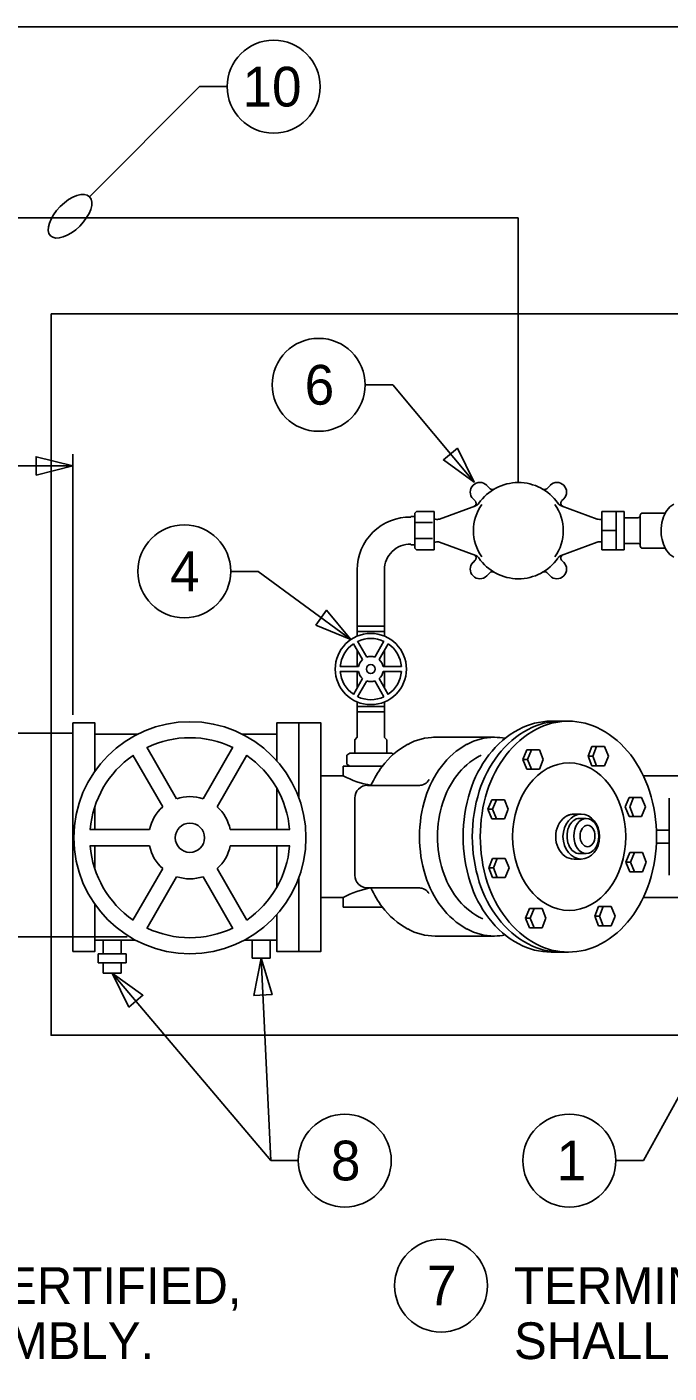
# Model space of a CAD drawing. Extents: x 10462 to 10511.2, y 10121.5 to 10170.9.
# Drawn here: x 10480.39 to 10492.04, y 10146.47 to 10170.89 of the extents above; entities that cross this region are included whole.
import ezdxf

# ---------------------------------------------------------------- set-up
doc = ezdxf.new("R2010")
doc.units = 0
for name, color, linetype in [('G-ANNO-NPLT', 7, 'Continuous'), ('G-ANNO-SYMB', 7, 'Continuous'), ('G-DETL-LINE', 7, 'Continuous'), ('G-DETL-TEXT', 7, 'Continuous')]:
    doc.layers.add(name, color=color, linetype=linetype)

msp = doc.modelspace()

# ---------------------------------------------------------------- linework, layer by layer
at = {"layer": 'G-ANNO-NPLT'}
msp.add_lwpolyline([(10462.021, 10170.89), (10511.163, 10170.89), (10511.163, 10125.39), (10462.021, 10125.39)], close=True, dxfattribs=at)
at = {"layer": 'G-ANNO-SYMB'}
for centre in [(10484.866, 10169.807), (10485.682, 10164.398), (10483.244, 10161.015), (10486.156, 10150.327), (10490.229, 10150.327), (10487.902, 10148.059)]:
    msp.add_circle(centre, 0.843, dxfattribs=at)
at = {"layer": 'G-DETL-LINE'}
for p, q in [((10469.431, 10167.426), (10489.303, 10167.426)), ((10489.303, 10162.626), (10489.303, 10167.426)), ((10486.525, 10164.398), (10487.025, 10164.398)), ((10488.501, 10162.632), (10487.025, 10164.398)), ((10488.73, 10162.575), (10488.791, 10162.514)), ((10489.88, 10162.575), (10489.819, 10162.514)), ((10487.875, 10161.964), (10488.531, 10162.206)), ((10488.483, 10162.328), (10488.521, 10162.291)), ((10490.735, 10161.964), (10490.079, 10162.206)), ((10490.127, 10162.328), (10490.089, 10162.291)), ((10487.355, 10162.011), (10487.428, 10162.011)), ((10487.428, 10162.073), (10487.457, 10162.103)), ((10487.428, 10162.073), (10487.428, 10161.433)), ((10487.744, 10161.899), (10487.428, 10161.899)), ((10487.777, 10162.103), (10487.457, 10162.103)), ((10487.777, 10162.103), (10487.777, 10161.899)), ((10487.777, 10161.899), (10487.777, 10161.753)), ((10487.835, 10161.957), (10487.817, 10161.957)), ((10490.775, 10161.957), (10490.793, 10161.957)), ((10490.817, 10161.404), (10490.817, 10162.103)), ((10490.817, 10162.103), (10491.224, 10162.103)), ((10491.079, 10161.404), (10491.079, 10162.103)), ((10491.224, 10161.404), (10491.224, 10162.103)), ((10491.474, 10161.986), (10491.224, 10161.986)), ((10491.515, 10161.479), (10491.515, 10162.031)), ((10491.515, 10162.028), (10491.515, 10162.031)), ((10491.557, 10162.073), (10491.971, 10162.073)), ((10487.777, 10161.753), (10487.777, 10161.404)), ((10490.817, 10161.753), (10491.079, 10161.753)), ((10487.355, 10161.495), (10487.428, 10161.495)), ((10487.744, 10161.608), (10487.428, 10161.608)), ((10487.428, 10161.433), (10487.457, 10161.404)), ((10487.835, 10161.55), (10487.817, 10161.55)), ((10487.875, 10161.542), (10488.531, 10161.301)), ((10490.735, 10161.542), (10490.079, 10161.301)), ((10490.775, 10161.55), (10490.793, 10161.55)), ((10491.474, 10161.521), (10491.224, 10161.521)), ((10491.515, 10161.475), (10491.515, 10161.479)), ((10491.557, 10161.433), (10491.971, 10161.433)), ((10487.777, 10161.404), (10487.457, 10161.404)), ((10488.483, 10161.178), (10488.521, 10161.216)), ((10490.127, 10161.178), (10490.089, 10161.216)), ((10490.817, 10161.404), (10491.224, 10161.404)), ((10484.087, 10161.015), (10484.587, 10161.015)), ((10486.263, 10159.779), (10484.587, 10161.015)), ((10486.381, 10161.041), (10486.381, 10159.84)), ((10486.875, 10161.041), (10486.875, 10159.84)), ((10488.73, 10160.931), (10488.791, 10160.992)), ((10489.88, 10160.931), (10489.819, 10160.992)), ((10486.381, 10160.022), (10486.875, 10160.022)), ((10486.477, 10159.415), (10486.311, 10159.703)), ((10486.381, 10159.925), (10486.875, 10159.925)), ((10486.554, 10159.46), (10486.388, 10159.748)), ((10486.867, 10159.748), (10486.701, 10159.46)), ((10486.945, 10159.703), (10486.779, 10159.415)), ((10486.381, 10159.581), (10486.381, 10159.289)), ((10486.875, 10159.581), (10486.875, 10159.289)), ((10486.403, 10159.289), (10486.071, 10159.289)), ((10487.184, 10159.289), (10486.852, 10159.289)), ((10486.403, 10159.198), (10486.071, 10159.198)), ((10486.477, 10159.071), (10486.311, 10158.784)), ((10486.381, 10159.198), (10486.381, 10158.906)), ((10486.554, 10159.027), (10486.388, 10158.739)), ((10486.867, 10158.739), (10486.701, 10159.027)), ((10486.945, 10158.784), (10486.779, 10159.071)), ((10487.184, 10159.198), (10486.852, 10159.198)), ((10486.875, 10159.198), (10486.875, 10158.906)), ((10486.381, 10158.647), (10486.381, 10158.465)), ((10486.381, 10158.647), (10486.381, 10158.004)), ((10486.381, 10158.562), (10486.875, 10158.562)), ((10486.875, 10158.647), (10486.875, 10158.465)), ((10486.875, 10158.647), (10486.875, 10158.004)), ((10486.381, 10158.465), (10486.875, 10158.465)), ((10489.9, 10158.297), (10490.212, 10158.297)), ((10481.224, 10158.081), (10478.077, 10158.081)), ((10482.399, 10158.063), (10481.624, 10158.063)), ((10484.922, 10158.063), (10484.292, 10158.063)), ((10486.383, 10158.007), (10486.337, 10157.96)), ((10486.872, 10158.007), (10486.919, 10157.96)), ((10487.762, 10158.005), (10488.871, 10158.006)), ((10482.565, 10157.827), (10483.106, 10156.89)), ((10483.585, 10156.89), (10484.126, 10157.827)), ((10486.337, 10157.96), (10486.337, 10157.716)), ((10486.919, 10157.96), (10486.918, 10157.716)), ((10489.387, 10157.601), (10489.456, 10157.775)), ((10489.54, 10157.775), (10489.456, 10157.775)), ((10489.471, 10157.601), (10489.54, 10157.775)), ((10489.54, 10157.775), (10489.685, 10157.775)), ((10489.755, 10157.601), (10489.685, 10157.775)), ((10490.57, 10157.662), (10490.639, 10157.836)), ((10490.723, 10157.836), (10490.639, 10157.836)), ((10490.654, 10157.662), (10490.723, 10157.836)), ((10490.723, 10157.836), (10490.868, 10157.835)), ((10490.938, 10157.662), (10490.868, 10157.835)), ((10482.312, 10157.681), (10482.853, 10156.744)), ((10483.838, 10156.744), (10484.379, 10157.681)), ((10486.191, 10157.682), (10486.25, 10157.716)), ((10486.191, 10157.517), (10486.191, 10157.682)), ((10486.191, 10157.517), (10486.25, 10157.483)), ((10486.25, 10157.716), (10487.006, 10157.716)), ((10487.034, 10157.699), (10487.006, 10157.716)), ((10489.471, 10157.601), (10489.387, 10157.601)), ((10489.456, 10157.427), (10489.387, 10157.601)), ((10489.54, 10157.427), (10489.471, 10157.601)), ((10489.685, 10157.426), (10489.755, 10157.601)), ((10490.654, 10157.662), (10490.57, 10157.662)), ((10490.639, 10157.487), (10490.57, 10157.662)), ((10490.723, 10157.487), (10490.654, 10157.662)), ((10490.868, 10157.487), (10490.938, 10157.662)), ((10485.724, 10157.308), (10486.126, 10157.308)), ((10486.126, 10157.482), (10486.839, 10157.482)), ((10486.126, 10157.482), (10486.126, 10157.308)), ((10489.54, 10157.427), (10489.456, 10157.427)), ((10489.685, 10157.426), (10489.54, 10157.427)), ((10490.723, 10157.487), (10490.639, 10157.487)), ((10490.868, 10157.487), (10490.723, 10157.487)), ((10491.572, 10157.308), (10492.422, 10157.308)), ((10486.57, 10157.133), (10487.515, 10157.133)), ((10486.338, 10156.901), (10486.338, 10155.505)), ((10488.752, 10156.699), (10488.821, 10156.873)), ((10488.906, 10156.873), (10488.821, 10156.873)), ((10488.836, 10156.699), (10488.906, 10156.873)), ((10488.906, 10156.873), (10489.051, 10156.872)), ((10489.121, 10156.699), (10489.051, 10156.872)), ((10491.243, 10156.741), (10491.312, 10156.915)), ((10491.396, 10156.915), (10491.312, 10156.915)), ((10491.327, 10156.741), (10491.396, 10156.915)), ((10491.396, 10156.915), (10491.541, 10156.915)), ((10491.612, 10156.741), (10491.541, 10156.915)), ((10492.038, 10156.901), (10492.038, 10155.505)), ((10488.821, 10156.524), (10488.752, 10156.699)), ((10488.836, 10156.699), (10488.752, 10156.699)), ((10488.906, 10156.524), (10488.836, 10156.699)), ((10489.051, 10156.524), (10489.121, 10156.699)), ((10490.314, 10156.61), (10490.446, 10156.61)), ((10490.414, 10156.534), (10490.537, 10156.534)), ((10491.312, 10156.566), (10491.243, 10156.741)), ((10491.396, 10156.566), (10491.312, 10156.566)), ((10491.396, 10156.566), (10491.327, 10156.741)), ((10491.541, 10156.566), (10491.396, 10156.566)), ((10491.541, 10156.566), (10491.612, 10156.741)), ((10481.532, 10156.332), (10482.614, 10156.332)), ((10484.077, 10156.332), (10485.16, 10156.332)), ((10488.906, 10156.524), (10488.821, 10156.524)), ((10489.051, 10156.524), (10488.906, 10156.524)), ((10491.808, 10156.319), (10492.038, 10156.319)), ((10491.808, 10156.086), (10492.038, 10156.086)), ((10481.532, 10156.034), (10482.614, 10156.034)), ((10484.077, 10156.034), (10485.16, 10156.034)), ((10488.767, 10155.634), (10488.836, 10155.808)), ((10488.92, 10155.808), (10488.836, 10155.808)), ((10488.851, 10155.634), (10488.92, 10155.808)), ((10488.92, 10155.808), (10489.065, 10155.808)), ((10489.135, 10155.634), (10489.065, 10155.808)), ((10490.314, 10155.795), (10490.446, 10155.795)), ((10490.414, 10155.894), (10490.537, 10155.894)), ((10491.256, 10155.742), (10491.325, 10155.916)), ((10491.409, 10155.916), (10491.325, 10155.916)), ((10491.34, 10155.742), (10491.409, 10155.916)), ((10491.409, 10155.916), (10491.554, 10155.915)), ((10491.624, 10155.742), (10491.554, 10155.915)), ((10482.312, 10154.685), (10482.853, 10155.623)), ((10483.838, 10155.623), (10484.379, 10154.685)), ((10488.851, 10155.634), (10488.767, 10155.634)), ((10488.836, 10155.46), (10488.767, 10155.634)), ((10488.92, 10155.46), (10488.851, 10155.634)), ((10489.065, 10155.459), (10489.135, 10155.634)), ((10491.34, 10155.742), (10491.256, 10155.742)), ((10491.325, 10155.567), (10491.256, 10155.742)), ((10491.409, 10155.567), (10491.325, 10155.567)), ((10491.409, 10155.567), (10491.34, 10155.742)), ((10491.554, 10155.567), (10491.409, 10155.567)), ((10491.554, 10155.567), (10491.624, 10155.742)), ((10482.565, 10154.539), (10483.106, 10155.476)), ((10483.585, 10155.476), (10484.126, 10154.539)), ((10488.92, 10155.46), (10488.836, 10155.46)), ((10489.065, 10155.459), (10488.92, 10155.46)), ((10485.724, 10155.097), (10486.126, 10155.097)), ((10486.126, 10154.923), (10486.126, 10155.097)), ((10486.57, 10155.272), (10487.515, 10155.272)), ((10491.572, 10155.097), (10492.422, 10155.097)), ((10486.126, 10154.923), (10486.839, 10154.923)), ((10489.436, 10154.724), (10489.505, 10154.898)), ((10489.589, 10154.898), (10489.505, 10154.898)), ((10489.52, 10154.724), (10489.589, 10154.898)), ((10489.589, 10154.898), (10489.734, 10154.897)), ((10489.804, 10154.724), (10489.734, 10154.897)), ((10490.69, 10154.76), (10490.759, 10154.934)), ((10490.844, 10154.934), (10490.759, 10154.934)), ((10490.774, 10154.76), (10490.844, 10154.934)), ((10490.844, 10154.934), (10490.989, 10154.934)), ((10491.059, 10154.76), (10490.989, 10154.934)), ((10489.52, 10154.724), (10489.436, 10154.724)), ((10489.505, 10154.549), (10489.436, 10154.724)), ((10489.589, 10154.549), (10489.52, 10154.724)), ((10489.734, 10154.549), (10489.804, 10154.724)), ((10490.774, 10154.76), (10490.69, 10154.76)), ((10490.759, 10154.585), (10490.69, 10154.76)), ((10490.844, 10154.585), (10490.759, 10154.585)), ((10490.844, 10154.585), (10490.774, 10154.76)), ((10490.989, 10154.585), (10490.844, 10154.585)), ((10490.989, 10154.585), (10491.059, 10154.76)), ((10482.211, 10154.388), (10478.077, 10154.388)), ((10487.796, 10154.399), (10488.871, 10154.399)), ((10489.589, 10154.549), (10489.505, 10154.549)), ((10489.734, 10154.549), (10489.589, 10154.549)), ((10482.362, 10154.323), (10481.624, 10154.323)), ((10481.773, 10154.079), (10481.773, 10154.323)), ((10482.099, 10154.323), (10482.099, 10154.079)), ((10484.922, 10154.323), (10484.33, 10154.323)), ((10484.478, 10154.323), (10484.478, 10153.997)), ((10484.803, 10153.997), (10484.803, 10154.323)), ((10490.212, 10154.108), (10489.9, 10154.108)), ((10481.685, 10154.079), (10482.187, 10154.079)), ((10481.685, 10154.079), (10481.685, 10153.911)), ((10481.685, 10154.079), (10481.685, 10154.079)), ((10481.685, 10153.911), (10482.187, 10153.911)), ((10481.685, 10153.911), (10481.685, 10153.911)), ((10481.773, 10153.726), (10481.773, 10153.911)), ((10482.099, 10153.911), (10482.099, 10153.726)), ((10482.187, 10154.079), (10482.187, 10153.911)), ((10482.187, 10154.079), (10482.187, 10154.079)), ((10482.187, 10153.911), (10482.187, 10153.911)), ((10484.478, 10153.997), (10484.803, 10153.997)), ((10482.099, 10153.726), (10481.773, 10153.726))]:
    msp.add_line(p, q, dxfattribs=at)
for points in [[(10488.202, 10163.25), (10488.501, 10162.632), (10487.946, 10163.036)], [(10485.628, 10160.04), (10486.263, 10159.779), (10485.825, 10160.308)]]:
    msp.add_lwpolyline(points, close=True, dxfattribs=at)
for points in [[(10481.624, 10154.972), (10481.624, 10154.12), (10481.224, 10154.12), (10481.224, 10158.265), (10481.624, 10158.265), (10481.624, 10157.394)], [(10484.922, 10157.577), (10484.922, 10158.265), (10485.323, 10158.265), (10485.323, 10156.904)], [(10485.323, 10156.904), (10485.323, 10158.265), (10485.724, 10158.265), (10485.724, 10154.12), (10485.323, 10154.12), (10485.323, 10155.462)], [(10484.922, 10156.332), (10484.922, 10157.08)], [(10481.624, 10156.755), (10481.624, 10156.332)], [(10481.624, 10156.034), (10481.624, 10155.611)], [(10484.922, 10155.286), (10484.922, 10156.034)], [(10485.323, 10155.462), (10485.323, 10154.12), (10484.922, 10154.12), (10484.922, 10154.789)]]:
    msp.add_lwpolyline(points, dxfattribs=at)
for centre, radius in [((10486.628, 10159.243), 0.646), ((10486.628, 10159.243), 0.0812), ((10483.346, 10156.183), 2.105), ((10483.346, 10156.183), 0.265)]:
    msp.add_circle(centre, radius, dxfattribs=at)
for centre, radius, start, end in [((10488.607, 10162.452), 0.175, 45, 225), ((10489.305, 10161.753), 0.873, 34.8669, 145.4138), ((10488.832, 10162.555), 0.0582, 225, 300.5225), ((10489.778, 10162.555), 0.0582, 239.4775, 315), ((10490.003, 10162.452), 0.175, 315, 135), ((10489.305, 10161.753), 0.815, 144.4495, 215.5505), ((10488.48, 10162.249), 0.0582, 290.6723, 45), ((10488.49, 10162.315), 0.116, 290.2165, 325.4138), ((10489.305, 10161.753), 0.815, 324.4495, 35.5505), ((10490.119, 10162.315), 0.116, 214.5862, 249.7835), ((10490.13, 10162.249), 0.0582, 135, 249.3277), ((10492.329, 10161.891), 0.401, 120.8869, 145.299), ((10487.34, 10161.041), 0.959, 89.096, 180), ((10487.817, 10162.015), 0.0582, 226.7551, 270), ((10487.835, 10162.073), 0.116, 270, 290.2165), ((10490.775, 10162.073), 0.116, 249.7835, 270), ((10490.793, 10162.015), 0.0582, 270, 294.5834), ((10491.474, 10162.028), 0.0419, 270, 0), ((10491.557, 10162.031), 0.0419, 90, 180), ((10492.639, 10161.753), 0.745, 163.9957, 181.5323), ((10492.449, 10161.808), 0.547, 145.299, 163.9957), ((10492.639, 10161.753), 0.745, 181.5323, 196.0043), ((10487.34, 10161.041), 0.466, 88.1376, 180), ((10487.817, 10161.491), 0.0582, 90, 133.2449), ((10487.835, 10161.433), 0.116, 69.7835, 90), ((10490.775, 10161.433), 0.116, 90, 110.2165), ((10490.793, 10161.491), 0.0582, 65.4166, 90), ((10491.474, 10161.479), 0.0419, 0, 90), ((10491.557, 10161.475), 0.0419, 180, 270), ((10492.449, 10161.699), 0.547, 196.0043, 214.701), ((10488.607, 10161.055), 0.175, 135, 315), ((10488.48, 10161.257), 0.0582, 315, 69.3277), ((10488.49, 10161.192), 0.116, 34.5862, 69.7835), ((10489.305, 10161.753), 0.873, 214.5862, 325.1331), ((10490.003, 10161.055), 0.175, 225, 45), ((10490.119, 10161.192), 0.116, 110.2165, 145.4138), ((10490.13, 10161.257), 0.0582, 110.6723, 225), ((10492.329, 10161.615), 0.401, 214.701, 239.1131), ((10488.832, 10160.951), 0.0582, 59.4775, 135), ((10489.778, 10160.951), 0.0582, 45, 120.5225), ((10486.628, 10159.243), 0.556, 124.6295, 175.2858), ((10486.628, 10159.243), 0.556, 64.6295, 115.3705), ((10486.628, 10159.243), 0.556, 4.7142, 55.3705), ((10486.628, 10159.243), 0.229, 71.3127, 108.6873), ((10486.628, 10159.243), 0.229, 131.3127, 168.4779), ((10486.628, 10159.243), 0.229, 11.5221, 48.6873), ((10486.628, 10159.243), 0.556, 184.7142, 235.3705), ((10486.628, 10159.243), 0.229, 191.5221, 228.6873), ((10486.628, 10159.243), 0.229, 251.3127, 288.6873), ((10486.628, 10159.243), 0.229, 311.3127, 348.4779), ((10486.628, 10159.243), 0.556, 304.6295, 355.2858), ((10486.628, 10159.243), 0.556, 244.6295, 295.3705), ((10489.9, 10157.063), 1.234, 90, 118.4823), ((10490.068, 10157.063), 1.234, 90, 118.4823), ((10490.212, 10157.063), 1.234, 90, 118.4823), ((10490.212, 10157.063), 1.234, 61.5177, 90), ((10483.346, 10156.183), 1.814, 64.6295, 115.3705), ((10487.796, 10156.969), 1.036, 90, 118.7905), ((10487.796, 10156.969), 1.036, 88.161, 90), ((10488.871, 10156.969), 1.036, 90, 118.7905), ((10490.125, 10156.649), 1.705, 118.4823, 142.6401), ((10488.871, 10156.969), 1.036, 79.0253, 90), ((10490.293, 10156.649), 1.705, 118.4823, 142.6401), ((10490.437, 10156.649), 1.705, 118.4823, 142.6401), ((10489.987, 10156.649), 1.705, 37.3599, 61.5177), ((10487.999, 10156.6), 1.458, 118.7905, 142.993), ((10489.074, 10156.6), 1.458, 118.7905, 142.993), ((10483.346, 10156.183), 1.814, 124.6295, 175.2858), ((10483.346, 10156.183), 1.814, 4.7142, 55.3705), ((10489.204, 10156.539), 1.277, 118.54, 142.7064), ((10490.478, 10156.379), 2.15, 142.6401, 162.4514), ((10489.034, 10156.852), 0.921, 116.0419, 118.54), ((10490.646, 10156.379), 2.15, 142.6401, 162.4514), ((10490.79, 10156.379), 2.15, 142.6401, 162.4514), ((10489.633, 10156.379), 2.15, 17.5486, 37.3599), ((10486.91, 10158.765), 1.655, 241.7189, 260.4318), ((10488.319, 10156.36), 1.857, 142.993, 155.3864), ((10489.393, 10156.36), 1.857, 142.993, 162.661), ((10489.472, 10156.336), 1.613, 142.7064, 162.4909), ((10486.57, 10156.901), 0.233, 90, 180), ((10487.508, 10157.339), 0.206, 267.8882, 330.0944), ((10491.036, 10156.203), 2.734, 162.4514, 180), ((10491.203, 10156.203), 2.734, 162.4514, 180), ((10491.347, 10156.203), 2.734, 162.4514, 180), ((10489.076, 10156.203), 2.734, 0, 17.5486), ((10483.346, 10156.183), 0.746, 71.3127, 108.6873), ((10489.896, 10156.203), 2.385, 162.661, 180), ((10489.893, 10156.203), 2.056, 162.4909, 180), ((10483.346, 10156.183), 0.746, 131.3127, 168.4779), ((10483.346, 10156.183), 0.746, 11.5221, 48.6873), ((10490.314, 10156.337), 0.273, 90, 116.9105), ((10490.446, 10156.337), 0.273, 90, 116.9105), ((10489.896, 10156.203), 2.385, 180, 197.339), ((10489.893, 10156.203), 2.056, 180, 197.5091), ((10491.036, 10156.203), 2.734, 180, 197.5486), ((10491.203, 10156.203), 2.734, 180, 197.5486), ((10491.347, 10156.203), 2.734, 180, 197.5486), ((10489.076, 10156.203), 2.734, 342.4514, 0), ((10483.346, 10156.183), 1.814, 184.7142, 235.3705), ((10483.346, 10156.183), 0.746, 191.5221, 228.6873), ((10483.346, 10156.183), 0.746, 311.3127, 348.4779), ((10483.346, 10156.183), 1.814, 304.6295, 355.2858), ((10489.51, 10156.203), 1.741, 342.3955, 348.0705), ((10489.472, 10156.07), 1.613, 197.5091, 217.2936), ((10483.346, 10156.183), 0.746, 251.3127, 288.6873), ((10486.57, 10155.505), 0.233, 180, 270), ((10489.393, 10156.045), 1.857, 197.339, 217.007), ((10490.478, 10156.026), 2.15, 197.5486, 217.3599), ((10490.646, 10156.026), 2.15, 197.5486, 217.3599), ((10490.79, 10156.026), 2.15, 197.5486, 217.3599), ((10489.633, 10156.026), 2.15, 322.6401, 342.4514), ((10486.91, 10153.64), 1.655, 99.5682, 118.2811), ((10488.319, 10156.045), 1.857, 204.6136, 217.007), ((10487.508, 10155.066), 0.206, 29.9056, 92.1118), ((10489.204, 10155.866), 1.277, 217.2936, 241.46), ((10487.999, 10155.805), 1.458, 217.007, 241.2095), ((10489.074, 10155.805), 1.458, 217.007, 241.2095), ((10489.034, 10155.553), 0.921, 241.46, 246.2039), ((10490.125, 10155.756), 1.705, 217.3599, 241.5177), ((10490.293, 10155.756), 1.705, 217.3599, 241.5177), ((10490.437, 10155.756), 1.705, 217.3599, 241.5177), ((10489.987, 10155.756), 1.705, 298.4823, 322.6401), ((10483.346, 10156.183), 1.814, 244.6295, 295.3705), ((10487.796, 10155.436), 1.036, 241.2095, 270), ((10488.871, 10155.436), 1.036, 241.2095, 270), ((10488.871, 10155.436), 1.036, 270, 280.9747), ((10489.9, 10155.342), 1.234, 241.5177, 270), ((10490.068, 10155.342), 1.234, 241.5177, 270), ((10490.212, 10155.342), 1.234, 241.5177, 270), ((10490.212, 10155.342), 1.234, 270, 298.4823)]:
    msp.add_arc(centre, radius, start, end, dxfattribs=at)
for centre, major_axis, ratio in [((10490.226, 10156.203), (0, 1.338), 0.766042), ((10490.446, 10156.203), (0, 0.407), 0.816083), ((10490.537, 10156.214), (0, 0.32), 0.711467), ((10490.559, 10156.214), (0, 0.195), 0.69425)]:
    msp.add_ellipse(centre, major_axis=major_axis, ratio=ratio, dxfattribs=at)
for centre, major_axis, ratio in [((10490.314, 10156.203), (0, 0.407), 0.816083), ((10490.414, 10156.214), (0, 0.32), 0.707873)]:
    msp.add_ellipse(centre, major_axis=major_axis, ratio=ratio, start_param=0, end_param=3.141593, dxfattribs=at)
at = {"layer": 'G-DETL-TEXT'}
for p, q in [((10483.523, 10169.807), (10481.526, 10167.81)), ((10483.523, 10169.807), (10484.023, 10169.807)), ((10481.224, 10158.414), (10481.224, 10163.138)), ((10481.224, 10162.926), (10473.577, 10162.926)), ((10484.641, 10153.997), (10484.814, 10150.327)), ((10481.936, 10153.726), (10484.814, 10150.327)), ((10492.825, 10152.6), (10491.572, 10150.327)), ((10485.314, 10150.327), (10484.814, 10150.327)), ((10491.572, 10150.327), (10491.072, 10150.327))]:
    msp.add_line(p, q, dxfattribs=at)
for points in [[(10480.829, 10165.686), (10502.918, 10165.686), (10502.918, 10152.6), (10480.829, 10152.6)], [(10480.557, 10162.76), (10481.224, 10162.926), (10480.557, 10163.093)], [(10484.506, 10153.323), (10484.641, 10153.997), (10484.838, 10153.339)], [(10482.24, 10153.11), (10481.936, 10153.726), (10482.494, 10153.325)]]:
    msp.add_lwpolyline(points, close=True, dxfattribs=at)
msp.add_ellipse((10481.172, 10167.456), major_axis=(-0.354, -0.354), ratio=0.5, dxfattribs=at)

# ---------------------------------------------------------------- texts
at = {"layer": 'G-ANNO-SYMB'}
for s, height, p in [('10', 0.7208, (10484.3, 10169.446)), ('6', 0.721, (10485.428, 10164.038)), ('4', 0.721, (10482.986, 10160.655)), ('8', 0.721, (10485.904, 10149.967)), ('1', 0.721, (10489.999, 10149.967)), ('7', 0.721, (10487.649, 10147.699))]:
    msp.add_text(s, height=height, dxfattribs=at).set_placement(p)
at = {"layer": 'G-DETL-TEXT'}
for s, p in [('U.L. AND F.M. APPROVED, ASSE CERTIFIED,', (10465.212, 10147.726)), ('TERMINATION OF DUCTILE IRON PIPE', (10489.225, 10147.726)), ('DOUBLE CHECK DETECTOR ASSEMBLY.', (10465.212, 10146.726)), ('SHALL BE THREADED AND EQUIPPED', (10489.225, 10146.726))]:
    msp.add_text(s, height=0.66667, dxfattribs=at).set_placement(p)

doc.saveas('drawing.dxf')
